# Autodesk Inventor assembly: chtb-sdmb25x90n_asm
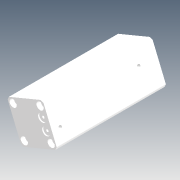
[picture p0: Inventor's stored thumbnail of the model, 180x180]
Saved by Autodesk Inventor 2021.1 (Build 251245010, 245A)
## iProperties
Company: Microsoft
Created: 2018-05
Part Number: chtb-sdmb25x90n_asm
Description: STEP AP214
Document SubType Name: Assembly
Designer: user
Title: chtb-sdmb25x90n_asm.STEP
Author: Windows
Revision Number: ÈÎºÎ
Sending System: SolidWorks 2015
Preprocessor: SwSTEP 2.0
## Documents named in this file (4)
- D:\Vault_2016\Projekty\Clamptek\Hydraulic\CHTB\CHTB-25\Inventor\chtb-sdmb25x90n\chtb-sdmb25x90n_asm.iam
- D:\Vault_2016\Projekty\Clamptek\Hydraulic\CHTB\CHTB-25\Inventor\chtb-sdmb25x90n\CHTB-25QG.ipt
- D:\Vault_2016\Projekty\Clamptek\Hydraulic\CHTB\CHTB-25\Inventor\chtb-sdmb25x90n\CHTB-SDMB25X90NBT.ipt
- D:\Vault_2016\Projekty\Clamptek\Hydraulic\CHTB\CHTB-25\Inventor\chtb-sdmb25x90n\CHTB-SDMB25X90NHSG.ipt
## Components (3 placed, 3 different names)
1. CHTB-25QG_1
2. CHTB-SDMB25X90NBT_2
3. CHTB-SDMB25X90NHSG_3
